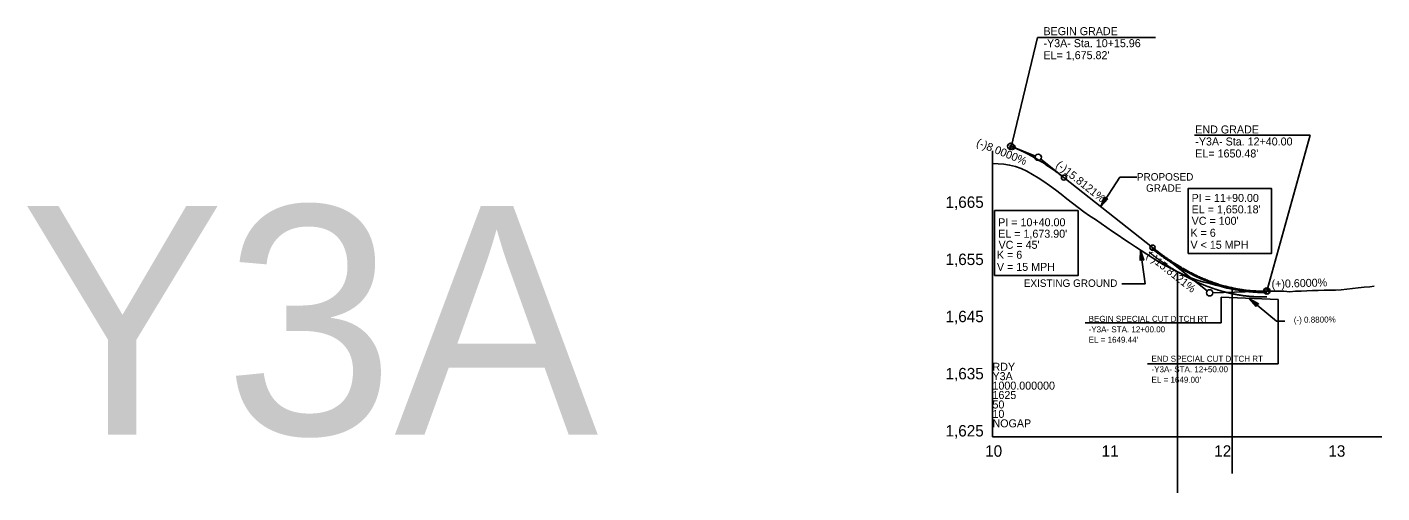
# Model space of a CAD drawing. Extents: x 498575 to 532350, y 405181 to 484585.
# Drawn here: x 505012 to 506197, y 458446 to 458853 of the extents above; entities that cross this region are included whole.
import ezdxf

# ---------------------------------------------------------------- set-up
doc = ezdxf.new("R2010")
doc.units = 0
for name, color, linetype in [('Exist Profile Cell', 7, 'Continuous'), ('Exist Vertical Profile Ground Line', 7, 'Continuous'), ('Exist Vertical Profile Horizontal Axis Label Major', 7, 'Continuous'), ('Exist Vertical Profile Vertical Axis Label', 7, 'Continuous'), ('Prop Grid Mask', 7, 'Continuous'), ('Prop PFL Text', 7, 'Continuous'), ('Prop Vertical Profile Curve Label', 7, 'Continuous'), ('Prop Vertical Profile Ditch Grade Right', 7, 'Continuous'), ('Prop Vertical Profile Ditch Grade Right Label', 7, 'Continuous'), ('Prop Vertical Profile Grade', 7, 'Continuous'), ('Prop Vertical Profile Grade Label', 7, 'Continuous'), ('Prop VPI Label', 7, 'Continuous'), ('Scratch_Level_5', 7, 'Continuous'), ('Scratch_Level_7', 7, 'Continuous')]:
    doc.layers.add(name, color=color, linetype=linetype)

msp = doc.modelspace()

# ---------------------------------------------------------------- linework, layer by layer
at = {"layer": 'Exist Profile Cell'}
for q in [(505856.7, 458744.8), (506197.3, 458494.8), (505856.7, 458494.8)]:
    msp.add_line((505856.7, 458494.8), q, dxfattribs=at)
at = {"layer": 'Exist Vertical Profile Ground Line'}
msp.add_lwpolyline([(505856.7, 458733.9), (505861.7, 458733.5), (505866.7, 458733.1), (505871.7, 458732.4), (505876.7, 458731.2), (505881.7, 458729.5), (505886.7, 458727.1), (505891.7, 458724.3), (505896.7, 458721.3), (505901.7, 458718), (505906.7, 458714.5), (505911.7, 458710.7), (505916.7, 458706.9), (505921.7, 458703), (505926.7, 458699.1), (505931.7, 458695.3), (505936.7, 458691.6), (505941.7, 458688.1), (505946.7, 458684.7), (505951.7, 458681.4), (505956.7, 458677.8), (505961.7, 458674.4), (505966.7, 458671.1), (505971.7, 458667.6), (505976.7, 458664.3), (505981.7, 458661), (505986.7, 458657.7), (505991.7, 458654.4), (505996.7, 458651.3), (506001.7, 458648.2), (506006.7, 458645.2), (506011.7, 458642.5), (506016.7, 458639.9), (506021.7, 458637.6), (506026.7, 458635.4), (506031.7, 458633.3), (506036.7, 458631.5), (506041.7, 458630), (506046.7, 458628.7), (506051.7, 458627.5), (506056.7, 458626.2), (506061.7, 458624.8), (506066.7, 458623.9), (506071.7, 458623), (506076.7, 458622.5), (506081.7, 458622.3), (506086.7, 458622), (506091.7, 458622), (506096.7, 458622.2), (506101.7, 458622.1), (506106.7, 458622), (506111.7, 458622.1), (506116.7, 458621.7), (506121.7, 458622), (506126.7, 458622), (506131.7, 458622.5), (506136.7, 458622.7), (506141.7, 458622.7), (506146.7, 458622.9), (506151.7, 458622.9), (506156.7, 458623.1), (506161.7, 458623.4), (506166.7, 458623.8), (506171.7, 458624.4), (506176.7, 458625), (506181.7, 458625.5), (506186.7, 458626), (506190.7, 458626.4)], dxfattribs=at)
at = {"layer": 'Prop Grid Mask'}
for points in [[(506027.8, 458655.1), (506100.8, 458655.1), (506100.8, 458711.9), (506027.8, 458711.9)], [(505858.6, 458635.8), (505931.6, 458635.8), (505931.6, 458692.6), (505858.6, 458692.6)]]:
    msp.add_lwpolyline(points, close=True, dxfattribs=at)
at = {"layer": 'Prop PFL Text'}
for p, q in [((505951.4, 458696.1), (505968, 458722)), ((505982.9, 458722), (505968, 458722)), ((505990.3, 458628.5), (505986.2, 458658.1)), ((505969.9, 458628.5), (505990.3, 458628.5))]:
    msp.add_line(p, q, dxfattribs=at)
for points in [[(505957.5, 458702.8), (505951.4, 458696.1), (505954.8, 458704.6), (505955.6, 458702.7)], [(505985.9, 458649), (505986.2, 458658.1), (505989, 458649.3), (505987.3, 458650.3)]]:
    msp.add_lwpolyline(points, close=True, dxfattribs=at)
at = {"layer": 'Prop Vertical Profile Curve Label'}
for centre in [(505874.2, 458748.3), (505919.2, 458721.5), (505996.7, 458660.2), (506096.7, 458622.2)]:
    msp.add_circle(centre, 2.25, dxfattribs=at)
at = {"layer": 'Prop Vertical Profile Ditch Grade Right'}
msp.add_line((506056.7, 458617), (506106.7, 458614.8), dxfattribs=at)
at = {"layer": 'Prop Vertical Profile Ditch Grade Right Label'}
for p, q in [((506056.7, 458594.3), (506056.7, 458617)), ((506081.4, 458615.5), (506105, 458595.8)), ((506106.7, 458614.8), (506106.7, 458558.5)), ((506056.7, 458594.3), (505937.9, 458594.3)), ((506112.3, 458595.8), (506105, 458595.8)), ((506106.7, 458558.5), (505992.3, 458558.5))]:
    msp.add_line(p, q, dxfattribs=at)
msp.add_lwpolyline([(506087.3, 458608.6), (506081.4, 458615.5), (506089.4, 458611), (506087.4, 458610.5)], close=True, dxfattribs=at)
at = {"layer": 'Prop Vertical Profile Grade'}
for p, q in [((505872.7, 458748.9), (505874.2, 458748.3)), ((505919.2, 458721.5), (505996.7, 458660.2))]:
    msp.add_line(p, q, dxfattribs=at)
for points in [[(505874.2, 458748.3), (505875.1, 458747.9), (505876, 458747.5), (505876.9, 458747.1), (505877.8, 458746.8), (505878.7, 458746.4), (505879.6, 458746), (505880.5, 458745.6), (505881.4, 458745.1), (505882.3, 458744.7), (505883.2, 458744.3), (505884.1, 458743.9), (505885, 458743.4), (505885.9, 458743), (505886.8, 458742.5), (505887.7, 458742.1), (505888.6, 458741.6), (505889.5, 458741.1), (505890.4, 458740.6), (505891.3, 458740.1), (505892.2, 458739.6), (505893.1, 458739.1), (505894, 458738.6), (505894.9, 458738.1), (505895.8, 458737.6), (505896.7, 458737.1), (505897.6, 458736.5), (505898.5, 458736), (505899.4, 458735.4), (505900.3, 458734.9), (505901.2, 458734.3), (505902.1, 458733.7), (505903, 458733.1), (505903.9, 458732.5), (505904.8, 458731.9), (505905.7, 458731.3), (505906.6, 458730.7), (505907.5, 458730.1), (505908.4, 458729.5), (505909.3, 458728.9), (505910.2, 458728.2), (505911.1, 458727.6), (505912, 458726.9), (505912.9, 458726.3), (505913.8, 458725.6), (505914.7, 458724.9), (505915.6, 458724.3), (505916.5, 458723.6), (505917.4, 458722.9), (505918.3, 458722.2), (505919.2, 458721.5)], [(505996.7, 458660.2), (505998.7, 458658.6), (506000.7, 458657.1), (506002.7, 458655.6), (506004.7, 458654.1), (506006.7, 458652.7), (506008.7, 458651.3), (506010.7, 458649.9), (506012.7, 458648.6), (506014.7, 458647.3), (506016.7, 458646), (506018.7, 458644.8), (506020.7, 458643.6), (506022.7, 458642.4), (506024.7, 458641.3), (506026.7, 458640.2), (506028.7, 458639.1), (506030.7, 458638.1), (506032.7, 458637), (506034.7, 458636.1), (506036.7, 458635.1), (506038.7, 458634.2), (506040.7, 458633.3), (506042.7, 458632.5), (506044.7, 458631.7), (506046.7, 458630.9), (506048.7, 458630.2), (506050.7, 458629.5), (506052.7, 458628.8), (506054.7, 458628.1), (506056.7, 458627.5), (506058.7, 458626.9), (506060.7, 458626.4), (506062.7, 458625.9), (506064.7, 458625.4), (506066.7, 458625), (506068.7, 458624.5), (506070.7, 458624.2), (506072.7, 458623.8), (506074.7, 458623.5), (506076.7, 458623.2), (506078.7, 458622.9), (506080.7, 458622.7), (506082.7, 458622.5), (506084.7, 458622.4), (506086.7, 458622.3), (506088.7, 458622.2), (506090.7, 458622.1), (506092.7, 458622.1), (506094.7, 458622.1), (506096.7, 458622.2)]]:
    msp.add_spline(points, degree=3, dxfattribs=at)
at = {"layer": 'Prop VPI Label'}
for p, q in [((505896, 458844.2), (505872.7, 458747)), ((505896, 458844.2), (505999.3, 458844.2)), ((506033.4, 458758.5), (506134.5, 458758.5)), ((506134.5, 458758.5), (506096.7, 458622)), ((505874.2, 458748.3), (505894.2, 458740.3)), ((505919.2, 458721.5), (505898.9, 458737.5)), ((505996.7, 458660.2), (506044.6, 458622.4)), ((506096.7, 458622.2), (506049.5, 458620.7))]:
    msp.add_line(p, q, dxfattribs=at)
for centre in [(505872.7, 458748.9), (505896.7, 458739.3), (506046.7, 458620.7), (506096.7, 458622.2)]:
    msp.add_circle(centre, 2.75, dxfattribs=at)
at = {"layer": 'Scratch_Level_5'}
for p, q in [((506018.4, 458639.5), (506018.4, 458445.6)), ((506066.4, 458624), (506066.4, 458462.5))]:
    msp.add_line(p, q, dxfattribs=at)
for points in [[(505993.7, 458656.3), (505994.1, 458655.9), (505994.7, 458655.5), (505995.3, 458655), (505995.5, 458654.8), (505995.6, 458654.8), (505995.6, 458654.7), (505995.6, 458654.7), (505995.7, 458654.7), (505995.7, 458654.7), (505995.9, 458654.5), (505996.2, 458654.3), (505996.6, 458653.9), (505996.9, 458653.8), (505997.2, 458653.5), (505997.3, 458653.4), (505997.5, 458653.3), (505997.5, 458653.2), (505997.6, 458653.2), (505997.7, 458653.2), (505997.7, 458653.1), (505997.7, 458653.1), (505997.7, 458653.1), (505998.2, 458652.7), (505998.7, 458652.4), (505999.3, 458651.9), (505999.4, 458651.8), (505999.6, 458651.7), (505999.7, 458651.6), (506000.1, 458651.3), (506000.6, 458651), (506001, 458650.6), (506001.5, 458650.3), (506001.7, 458650.1), (506002.4, 458649.6), (506002.9, 458649.3), (506003.5, 458648.9), (506003.6, 458648.8), (506003.9, 458648.6), (506004, 458648.5), (506004.3, 458648.3), (506004.8, 458647.9), (506005.4, 458647.5), (506005.8, 458647.3), (506006, 458647.1), (506006, 458647.1), (506006.1, 458647), (506006.7, 458646.6), (506007.2, 458646.3), (506007.8, 458645.9), (506007.8, 458645.9), (506007.9, 458645.8), (506008, 458645.7), (506008.2, 458645.6), (506008.5, 458645.4), (506009.1, 458645), (506009.6, 458644.7), (506009.9, 458644.5), (506010, 458644.4), (506010.1, 458644.3), (506010.3, 458644.2), (506010.7, 458643.9), (506011.2, 458643.6), (506011.6, 458643.3), (506011.8, 458643.2), (506011.9, 458643.1), (506012, 458643.1), (506012.6, 458642.7), (506013.1, 458642.4), (506013.7, 458642), (506013.8, 458642), (506014, 458641.8), (506014, 458641.8), (506014.2, 458641.7), (506014.5, 458641.5), (506015, 458641.2), (506015.6, 458640.8), (506015.9, 458640.7), (506016, 458640.6), (506016.1, 458640.5), (506016.3, 458640.4), (506016.9, 458640.1), (506017.5, 458639.7), (506018.3, 458639.2), (506018.5, 458639.1), (506019, 458638.8), (506019.4, 458638.6), (506019.8, 458638.3), (506020, 458638.2), (506020.2, 458638.1), (506020.5, 458637.9), (506021, 458637.6), (506021.7, 458637.3), (506022.1, 458637), (506022.3, 458636.9), (506022.4, 458636.8), (506023.1, 458636.5), (506023.6, 458636.2), (506024.2, 458635.9), (506024.2, 458635.8), (506024.4, 458635.8), (506024.4, 458635.7), (506024.6, 458635.6), (506025, 458635.4), (506025.5, 458635.1), (506026, 458634.9), (506026.2, 458634.8), (506026.3, 458634.7), (506026.4, 458634.7), (506026.7, 458634.5), (506027.2, 458634.2), (506027.9, 458633.9), (506028.2, 458633.7), (506028.5, 458633.6), (506028.6, 458633.5), (506029.3, 458633.2), (506029.8, 458632.9), (506030.6, 458632.5), (506030.9, 458632.4), (506031.4, 458632.1), (506031.8, 458631.9), (506032.2, 458631.7), (506032.4, 458631.6), (506032.6, 458631.6), (506032.6, 458631.5), (506033, 458631.4), (506033.5, 458631.1), (506034, 458630.9), (506034.4, 458630.7), (506034.6, 458630.6), (506034.8, 458630.5), (506035.2, 458630.3), (506035.8, 458630.1), (506036.2, 458629.9), (506036.5, 458629.8), (506036.6, 458629.7), (506036.6, 458629.7), (506036.7, 458629.7), (506037.2, 458629.4), (506037.8, 458629.2), (506038.5, 458628.9), (506038.6, 458628.8), (506038.9, 458628.7), (506039, 458628.7), (506039.4, 458628.5), (506039.9, 458628.3), (506040.5, 458628), (506040.9, 458627.9), (506041, 458627.8), (506041.3, 458627.7), (506041.7, 458627.5), (506042.2, 458627.3), (506042.7, 458627.1), (506042.9, 458627), (506043.1, 458627), (506043.7, 458626.7), (506044.3, 458626.5), (506045, 458626.2), (506045.1, 458626.2), (506045.4, 458626.1), (506045.8, 458625.9), (506046.4, 458625.7), (506046.8, 458625.6), (506047.1, 458625.5), (506047.2, 458625.4), (506047.6, 458625.3), (506048.2, 458625.1), (506048.7, 458624.9), (506049.1, 458624.7), (506049.3, 458624.7), (506049.5, 458624.6), (506050, 458624.4), (506050.5, 458624.3), (506050.9, 458624.1), (506051.2, 458624), (506051.4, 458624), (506052.1, 458623.7), (506052.6, 458623.6), (506053.3, 458623.3), (506053.5, 458623.3), (506053.7, 458623.2), (506054.2, 458623.1), (506054.7, 458622.9), (506055.2, 458622.8), (506055.4, 458622.7), (506055.4, 458622.7), (506055.6, 458622.7), (506055.9, 458622.5), (506056.4, 458622.4), (506056.9, 458622.3), (506057.1, 458622.2), (506057.3, 458622.2), (506057.7, 458622), (506058.3, 458621.9), (506058.8, 458621.7), (506059.3, 458621.6), (506059.4, 458621.6), (506059.7, 458621.5), (506060.1, 458621.4), (506060.6, 458621.3), (506061.1, 458621.1), (506061.4, 458621.1), (506062.3, 458620.8), (506062.8, 458620.7), (506063.7, 458620.5), (506064, 458620.4), (506064.6, 458620.3), (506064.9, 458620.2), (506065.3, 458620.1), (506065.4, 458620.1), (506065.7, 458620.1), (506065.9, 458620), (506066.3, 458619.9), (506066.9, 458619.8), (506067.5, 458619.7), (506067.8, 458619.6), (506067.9, 458619.6), (506068, 458619.6), (506068.3, 458619.5), (506068.8, 458619.4), (506069.2, 458619.4), (506069.6, 458619.3), (506069.8, 458619.2), (506070.1, 458619.2), (506070.5, 458619.1), (506070.9, 458619), (506071.5, 458618.9), (506071.8, 458618.9), (506072.7, 458618.7), (506073.3, 458618.6), (506074.2, 458618.5), (506074.5, 458618.5), (506075, 458618.4), (506075.3, 458618.3), (506076.2, 458618.2), (506076.8, 458618.1), (506077.7, 458618), (506078, 458618), (506078.6, 458617.9), (506079.1, 458617.9), (506079.7, 458617.8), (506080.3, 458617.7), (506080.6, 458617.7), (506081.5, 458617.6), (506082.1, 458617.6), (506083, 458617.5), (506083.3, 458617.5), (506083.9, 458617.4), (506084.2, 458617.4), (506085, 458617.4), (506085.6, 458617.3), (506086.8, 458617.3), (506087.4, 458617.2), (506088.6, 458617.2), (506089.2, 458617.2), (506090.4, 458617.1), (506091, 458617.1), (506091.9, 458617.1), (506092.2, 458617.1), (506092.6, 458617.1), (506092.7, 458617.1), (506092.7, 458617.1), (506092.7, 458617.1), (506092.7, 458617.1), (506092.7, 458617.1), (506092.8, 458617.1), (506092.8, 458617.1), (506092.9, 458617.1), (506093, 458617.1), (506093.2, 458617.1), (506093.6, 458617.1), (506093.9, 458617.1), (506094.4, 458617.1), (506094.5, 458617.1), (506094.7, 458617.1), (506094.8, 458617.1), (506094.8, 458617.1), (506094.9, 458617.1), (506094.9, 458617.1), (506094.9, 458617.1), (506094.9, 458617.1), (506094.9, 458617.1), (506094.9, 458617.1), (506095, 458617.1), (506095.6, 458617.1), (506096.3, 458617.1), (506096.8, 458617.2)], [(505996.1, 458659.4), (505996.5, 458659), (505997.1, 458658.6), (505997.7, 458658.1), (505997.9, 458657.9), (505998, 458657.9), (505998.1, 458657.8), (505998.1, 458657.8), (505998.3, 458657.6), (505998.6, 458657.4), (505999, 458657.1), (505999.3, 458656.9), (505999.6, 458656.7), (505999.7, 458656.6), (505999.9, 458656.4), (506000, 458656.4), (506000, 458656.3), (506000.1, 458656.3), (506000.1, 458656.2), (506000.6, 458655.9), (506001.1, 458655.5), (506002, 458654.9), (506002.4, 458654.5), (506003.4, 458653.8), (506003.8, 458653.5), (506004.8, 458652.8), (506005.2, 458652.5), (506006.2, 458651.8), (506006.6, 458651.5), (506007.6, 458650.8), (506008, 458650.5), (506009, 458649.9), (506009.4, 458649.5), (506010.4, 458648.9), (506010.9, 458648.6), (506011.6, 458648.1), (506011.8, 458648), (506012.3, 458647.6), (506012.5, 458647.5), (506013, 458647.2), (506013.2, 458647), (506013.7, 458646.7), (506014, 458646.5), (506014.7, 458646.1), (506015.2, 458645.8), (506016.1, 458645.2), (506016.6, 458644.9), (506017.6, 458644.3), (506018.1, 458644), (506019.1, 458643.4), (506019.6, 458643.1), (506020.5, 458642.5), (506021, 458642.2), (506021.8, 458641.8), (506022, 458641.6), (506022.5, 458641.3), (506022.8, 458641.2), (506023.5, 458640.8), (506024, 458640.5), (506025, 458639.9), (506025.5, 458639.7), (506026.5, 458639.1), (506027, 458638.8), (506027.8, 458638.4), (506028, 458638.3), (506028.5, 458638), (506028.8, 458637.9), (506029.5, 458637.5), (506030.1, 458637.2), (506031.1, 458636.7), (506031.6, 458636.5), (506032.6, 458635.9), (506033.1, 458635.7), (506034.2, 458635.2), (506034.7, 458634.9), (506035.7, 458634.5), (506036.2, 458634.2), (506037, 458633.9), (506037.3, 458633.7), (506037.8, 458633.5), (506038.1, 458633.4), (506038.8, 458633), (506039.4, 458632.8), (506040.4, 458632.4), (506040.9, 458632.1), (506041.7, 458631.8), (506042, 458631.7), (506042.5, 458631.5), (506042.8, 458631.4), (506043.6, 458631), (506044.1, 458630.8), (506045.2, 458630.4), (506045.7, 458630.2), (506046.5, 458629.9), (506046.8, 458629.8), (506047.3, 458629.6), (506047.6, 458629.5), (506048.4, 458629.2), (506048.9, 458629), (506049.8, 458628.7), (506050, 458628.6), (506050.6, 458628.4), (506050.8, 458628.3), (506051.6, 458628), (506052.2, 458627.9), (506053.3, 458627.5), (506053.8, 458627.3), (506054.6, 458627.1), (506054.9, 458627), (506055.5, 458626.8), (506055.7, 458626.7), (506056.6, 458626.5), (506057.1, 458626.3), (506057.9, 458626.1), (506058.2, 458626), (506058.8, 458625.9), (506059, 458625.8), (506059.9, 458625.5), (506060.4, 458625.4), (506061.5, 458625.1), (506062.1, 458625), (506063.2, 458624.7), (506063.8, 458624.6), (506064.9, 458624.3), (506065.4, 458624.2), (506066.6, 458623.9), (506067.1, 458623.8), (506068.2, 458623.6), (506068.8, 458623.5), (506071.6, 458622.9), (506073.9, 458622.5), (506077.3, 458622.1), (506078.4, 458621.9), (506080.7, 458621.7), (506081.9, 458621.6), (506084.2, 458621.4), (506085.3, 458621.3), (506087.6, 458621.2), (506088.7, 458621.1), (506090.5, 458621.1), (506091, 458621.1), (506091.9, 458621.1), (506092.3, 458621.1), (506092.6, 458621.1), (506092.7, 458621.1), (506092.7, 458621.1), (506092.8, 458621.1), (506092.8, 458621.1), (506092.8, 458621.1), (506092.9, 458621.1), (506093, 458621.1), (506093.2, 458621.1), (506093.6, 458621.1), (506093.9, 458621.1), (506094.3, 458621.1), (506094.5, 458621.1), (506094.7, 458621.1), (506094.7, 458621.1), (506094.8, 458621.1), (506094.8, 458621.1), (506094.8, 458621.1), (506094.8, 458621.1), (506094.8, 458621.1), (506094.9, 458621.1), (506095.6, 458621.1), (506096.2, 458621.1), (506096.8, 458621.1)]]:
    msp.add_open_spline(points, degree=3, dxfattribs=at)

# ---------------------------------------------------------------- texts
at = {"layer": 'Exist Profile Cell'}
for s, p in [('Y3A', (505856.7, 458544.3)), ('RDY', (505856.7, 458552.5)), ('1000.000000', (505856.7, 458536)), ('50', (505856.7, 458519.5)), ('1625', (505856.7, 458527.8)), ('10', (505856.7, 458511.3)), ('NOGAP', (505856.7, 458503))]:
    msp.add_text(s, height=7, dxfattribs=at).set_placement(p)
at = {"layer": 'Exist Vertical Profile Horizontal Axis Label Major'}
for s, p in [('10', (505850.3, 458477.3)), ('11', (505952.2, 458477.3)), ('12', (506050.7, 458477.3)), ('13', (506150.5, 458477.3))]:
    msp.add_text(s, height=10, dxfattribs=at).set_placement(p)
at = {"layer": 'Exist Vertical Profile Vertical Axis Label'}
for s, p in [('1,665', (505815.6, 458695)), ('1,655', (505815.6, 458645)), ('1,645', (505815.6, 458595)), ('1,635', (505815.6, 458545)), ('1,625', (505815.6, 458495))]:
    msp.add_text(s, height=10, dxfattribs=at).set_placement(p)
at = {"layer": 'Prop PFL Text'}
for s, height, p in [('PROPOSED', 6.52, (505983, 458718.9)), ('GRADE', 6.52, (505991, 458709.1)), ('EXISTING GROUND', 6.516, (505884.1, 458625.9))]:
    msp.add_text(s, height=height, dxfattribs=at).set_placement(p)
at = {"layer": 'Prop Vertical Profile Curve Label'}
for s, p in [("VC = 100'", (506030.9, 458680.2)), ('K = 6', (506029.9, 458669.7)), ('K = 6', (505860.6, 458650.5)), ("VC = 45'", (505862, 458659.2)), ('V < 15 MPH ', (506029.9, 458659.2)), ('V = 15 MPH ', (505860.6, 458639.9))]:
    msp.add_text(s, height=7, dxfattribs=at).set_placement(p)
at = {"layer": 'Prop Vertical Profile Ditch Grade Right Label'}
for s, rotation, p in [('BEGIN SPECIAL CUT DITCH RT', 360, (505940.8, 458595.3)), ('(-) 0.8800%', 0.5967, (506120.3, 458594.4)), ('-Y3A- STA. 12+00.00', 360, (505940.8, 458586.1)), ("EL = 1649.44'", 360, (505940.8, 458577)), ('END SPECIAL CUT DITCH RT', 360, (505995.8, 458560.4)), ('-Y3A- STA. 12+50.00', 360, (505995.8, 458551.2)), ("EL = 1649.00'", 360, (505995.8, 458542))]:
    msp.add_text(s, height=5.25, rotation=rotation, dxfattribs=at).set_placement(p)
at = {"layer": 'Prop Vertical Profile Grade Label'}
for s, rotation, p in [('(-)8.0000%', 338.1986, (505842, 458749.5)), ('(-)15.8121%', 321.6699, (505911.5, 458731.4)), ('(-)15.8121%', 321.6699, (505990.7, 458652.3)), ('(+)0.6000%', 1.7184, (506100.9, 458624.9))]:
    msp.add_text(s, height=7, rotation=rotation, dxfattribs=at).set_placement(p)
at = {"layer": 'Prop VPI Label'}
for s, p in [('BEGIN GRADE', (505901.3, 458846.1)), ('-Y3A- Sta. 10+15.96', (505901.3, 458835.6)), ("EL= 1,675.82'", (505901.3, 458825.1)), ('END GRADE', (506034.1, 458760.1)), ('-Y3A- Sta. 12+40.00', (506034.1, 458749.6)), ("EL= 1650.48'", (506034.1, 458739.1)), ('PI = 11+90.00', (506030.9, 458700.2)), ("EL = 1,650.18'", (506030.9, 458690.2)), ('PI = 10+40.00', (505861.7, 458678.9)), ("EL = 1,673.90'", (505861.7, 458668.9))]:
    msp.add_text(s, height=7, dxfattribs=at).set_placement(p)
at = {"layer": 'Scratch_Level_7'}
msp.add_text('Y3A', height=200, dxfattribs=at).set_placement((505006.4, 458496.7))

doc.saveas('drawing.dxf')
